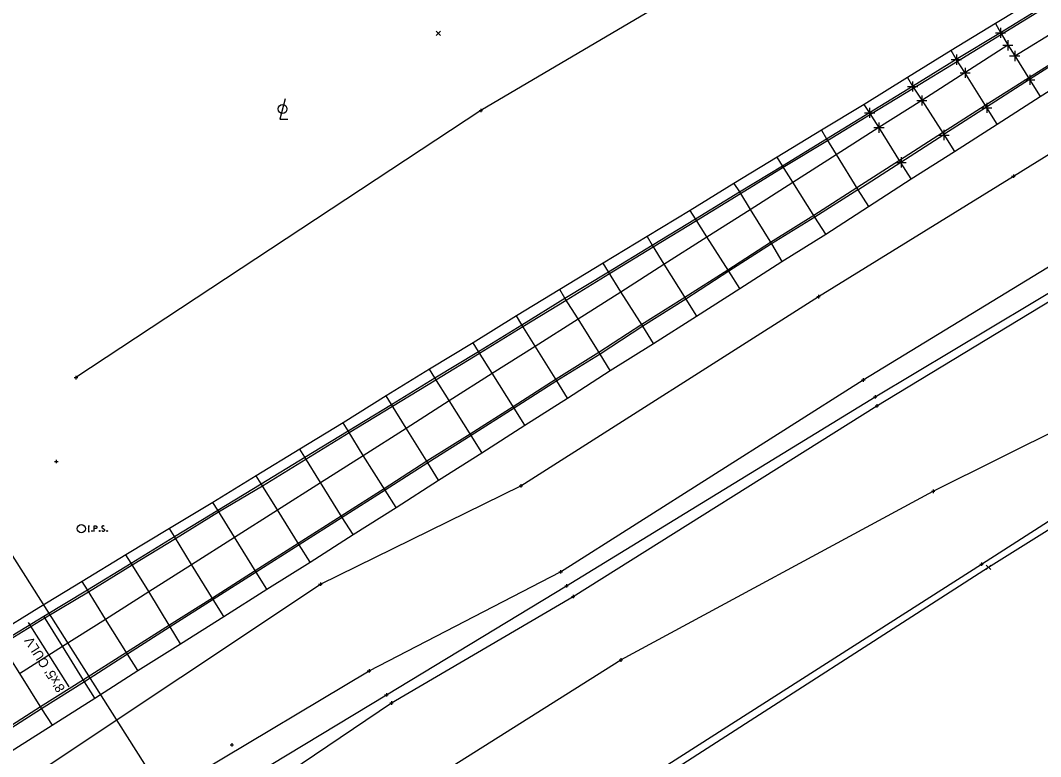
# Model space of a CAD drawing. Extents: x 207090 to 277928, y 600777 to 621109.
# Drawn here: x 261676.8 to 261977.3, y 611702.8 to 611919.6 of the extents above; entities that cross this region are included whole.
import ezdxf

# ---------------------------------------------------------------- set-up
doc = ezdxf.new("R2010")
doc.units = 0
for name, color, linetype in [('DR_X_Culvert', 7, 'Continuous'), ('DR_X_Ditch', 7, 'Continuous'), ('DR_X_Text', 7, 'Continuous'), ('LT_X_Poles', 7, 'Continuous'), ('PM_P_Dotted_Line', 7, 'Continuous'), ('PM_P_Edge_Line', 7, 'Continuous'), ('PM_P_Lane_Line', 7, 'Continuous'), ('PM_P_Stop_Line', 7, 'Continuous'), ('PM_X_Edge_Line', 7, 'Continuous'), ('PV_X_EOP', 7, 'Continuous'), ('PV_X_Joint', 7, 'Continuous'), ('PV_X_Shoulder', 7, 'Continuous'), ('SC_ProfileRun2', 7, 'Continuous'), ('SV_X_LiDAR_Check_Spots', 7, 'Continuous'), ('SV_X_Terrain_Boundary', 7, 'Continuous'), ('SV_X_Toe_of_Slope', 7, 'Continuous')]:
    doc.layers.add(name, color=color, linetype=linetype)

msp = doc.modelspace()

# ---------------------------------------------------------------- linework, layer by layer
at = {"layer": 'DR_X_Culvert'}
msp.add_line((261715.99, 611696.51), (261667.47, 611772.86), dxfattribs=at)
at = {"layer": 'DR_X_Ditch'}
msp.add_lwpolyline([(261132.11, 611543.06), (261151.34, 611551.01), (261204.82, 611549.24), (261275.42, 611542.1), (261338.97, 611540.56), (261396.89, 611545.27), (261464.5, 611556.09), (261526.91, 611576.88), (261579.68, 611599.94), (261643.38, 611630.11), (261702.06, 611671.1), (261784.56, 611720.96), (261837.63, 611753.06), (261928.54, 611808.72), (261986.01, 611843.07), (262043.42, 611883.09), (262136.97, 611939.5), (262196.81, 611979.61), (262342.79, 612067.36), (262434.39, 612121.89), (262514.3, 612151.84), (262581.31, 612172.43), (262656.49, 612183.09)], dxfattribs=at)
at = {"layer": 'DR_X_Text'}
msp.add_line((261679.01, 611742.21), (261691, 611723.34), dxfattribs=at)
at = {"layer": 'LT_X_Poles'}
msp.add_lwpolyline([(261754.78, 611896.47), (261753.2, 611890.49), (261755.57, 611890.49)], dxfattribs=at)
msp.add_circle((261753.99, 611893.52), 1.3, dxfattribs=at)
at = {"layer": 'PM_P_Dotted_Line'}
for points in [[(261696.72, 611770.7), (261697.08, 611770.7)], [(261696.72, 611769.1), (261697.08, 611769.1)], [(261696.9, 611769.1), (261696.9, 611770.7)], [(261697.86, 611769.31), (261697.92, 611769.31), (261697.95, 611769.28), (261697.98, 611769.23), (261697.98, 611769.17), (261697.95, 611769.12), (261697.92, 611769.1), (261697.86, 611769.1), (261697.83, 611769.12), (261697.79, 611769.17), (261697.79, 611769.23), (261697.83, 611769.28), (261697.86, 611769.31)], [(261698.47, 611769.1), (261698.47, 611770.7), (261699, 611770.7), (261699.05, 611770.68), (261699.13, 611770.66), (261699.16, 611770.63), (261699.19, 611770.61), (261699.24, 611770.54), (261699.27, 611770.48), (261699.29, 611770.38), (261699.29, 611770.23), (261699.28, 611770.18), (261699.26, 611770.1), (261699.22, 611770.02), (261699.17, 611769.98), (261699.14, 611769.95), (261699.08, 611769.93), (261699, 611769.91), (261698.47, 611769.91)], [(261700.11, 611769.31), (261700.16, 611769.31), (261700.2, 611769.28), (261700.23, 611769.23), (261700.23, 611769.17), (261700.2, 611769.12), (261700.16, 611769.1), (261700.11, 611769.1), (261700.08, 611769.12), (261700.04, 611769.17), (261700.04, 611769.23), (261700.08, 611769.28), (261700.11, 611769.31)], [(261701.48, 611770.58), (261701.45, 611770.61), (261701.42, 611770.63), (261701.32, 611770.67), (261701.2, 611770.7), (261701.11, 611770.7), (261701.08, 611770.7), (261700.94, 611770.66), (261700.81, 611770.58), (261700.74, 611770.48), (261700.72, 611770.38), (261700.72, 611770.3), (261700.74, 611770.2), (261700.83, 611770.12), (261701.43, 611769.74), (261701.49, 611769.69), (261701.51, 611769.64), (261701.53, 611769.56), (261701.53, 611769.49), (261701.52, 611769.41), (261701.51, 611769.36), (261701.49, 611769.3), (261701.46, 611769.25), (261701.44, 611769.21), (261701.41, 611769.17), (261701.38, 611769.15), (261701.33, 611769.12), (261701.3, 611769.11), (261701.2, 611769.1), (261701.05, 611769.1), (261700.95, 611769.12), (261700.8, 611769.21), (261700.72, 611769.28)], [(261702.29, 611769.31), (261702.35, 611769.31), (261702.38, 611769.28), (261702.41, 611769.23), (261702.41, 611769.17), (261702.38, 611769.12), (261702.35, 611769.1), (261702.29, 611769.1), (261702.26, 611769.12), (261702.23, 611769.17), (261702.23, 611769.23), (261702.26, 611769.28), (261702.29, 611769.31)]]:
    msp.add_lwpolyline(points, dxfattribs=at)
msp.add_circle((261694.71, 611769.89), 1.2, dxfattribs=at)
at = {"layer": 'PM_P_Edge_Line'}
for points in [[(261095.2, 611517.38), (261109.55, 611556.21), (261131.91, 611573.68), (261149.08, 611575.07), (261202.59, 611571.64), (261280.97, 611564.25), (261338.62, 611565.1), (261393.58, 611575.38), (261461.16, 611589.52), (261517.96, 611607.33), (261562.93, 611628.5), (261627.57, 611664.18), (261682.84, 611698.73), (261765.12, 611753.52), (261824.13, 611782.52), (261911.81, 611838.23), (261969.24, 611873.72), (262025.82, 611908.8), (262125.41, 611964.66), (262182.53, 612002.94), (262326.11, 612091.51)], [(261150.65, 611386.42), (261155.64, 611444.15), (261157.57, 611491.18), (261209.46, 611500.37), (261264.83, 611505.15), (261342.34, 611500.54), (261398.44, 611505.87), (261472.12, 611523.34), (261533.41, 611542.89), (261595.48, 611569.82), (261660.17, 611598), (261726.83, 611640.47), (261794.94, 611694.24), (261853.6, 611731.21), (261945.61, 611780.89), (262004.28, 611810.1), (262064.35, 611850.74), (262127.57, 611893.89), (262159.14, 611906.07), (262217.33, 611944.84), (262360.65, 612038.77)]]:
    msp.add_lwpolyline(points, dxfattribs=at)
at = {"layer": 'PM_P_Lane_Line'}
msp.add_lwpolyline([(261153.94, 611385.97), (261160.28, 611443.31), (261165.11, 611483.68), (261209.25, 611484.8), (261264.74, 611486.28), (261342.14, 611487.48), (261398.74, 611488.7), (261481.71, 611501.24), (261537, 611521.16), (261606, 611546.1), (261656.85, 611565.67), (261670.38, 611573.79), (261742.74, 611619.98), (261811.92, 611664.95), (261868.59, 611701.14), (261959.9, 611759.42), (262013.54, 611793.87), (262076.54, 611833.59), (262168.76, 611888.84), (262184.39, 611898.2), (262204.83, 611910.25), (262363.11, 611892.31)], dxfattribs=at)
at = {"layer": 'PM_P_Stop_Line'}
for p, q in [((261811.86, 611893.04), (261812.86, 611893.04)), ((261812.36, 611893.54), (261812.36, 611892.54)), ((261812.36, 611893.04), (261812.36, 611893.04)), ((261968.74, 611873.72), (261969.74, 611873.72)), ((261969.24, 611874.22), (261969.24, 611873.22)), ((261969.24, 611873.72), (261969.24, 611873.72)), ((261911.31, 611838.23), (261912.31, 611838.23)), ((261911.81, 611838.73), (261911.81, 611837.73)), ((261911.81, 611838.23), (261911.81, 611838.23)), ((261692.64, 611814.37), (261693.64, 611814.37)), ((261693.14, 611814.87), (261693.14, 611813.87)), ((261693.14, 611814.37), (261693.14, 611814.37)), ((261924.55, 611813.69), (261925.55, 611813.69)), ((261925.05, 611814.19), (261925.05, 611813.19)), ((261925.05, 611813.69), (261925.05, 611813.69)), ((261928.04, 611808.72), (261929.04, 611808.72)), ((261928.54, 611809.22), (261928.54, 611808.22)), ((261928.54, 611808.72), (261928.54, 611808.72)), ((261928.57, 611806.04), (261929.57, 611806.04)), ((261929.07, 611806.54), (261929.07, 611805.54)), ((261929.07, 611806.04), (261929.07, 611806.04)), ((261823.63, 611782.52), (261824.63, 611782.52)), ((261824.13, 611783.02), (261824.13, 611782.02)), ((261824.13, 611782.52), (261824.13, 611782.52)), ((261945.11, 611780.89), (261946.11, 611780.89)), ((261945.61, 611781.39), (261945.61, 611780.39)), ((261945.61, 611780.89), (261945.61, 611780.89)), ((261959.4, 611759.42), (261960.4, 611759.42)), ((261959.9, 611759.92), (261959.9, 611758.92)), ((261959.9, 611759.42), (261959.9, 611759.42)), ((261835.4, 611757.16), (261836.4, 611757.16)), ((261835.9, 611757.66), (261835.9, 611756.66)), ((261835.9, 611757.16), (261835.9, 611757.16)), ((261764.62, 611753.52), (261765.62, 611753.52)), ((261765.12, 611754.02), (261765.12, 611753.02)), ((261765.12, 611753.52), (261765.12, 611753.52)), ((261837.63, 611753.56), (261837.63, 611752.56)), ((261837.13, 611753.06), (261838.13, 611753.06)), ((261837.63, 611753.06), (261837.63, 611753.06)), ((261839.61, 611750.39), (261839.61, 611749.39)), ((261839.11, 611749.89), (261840.11, 611749.89)), ((261839.61, 611749.89), (261839.61, 611749.89)), ((261853.1, 611731.21), (261854.1, 611731.21)), ((261853.6, 611731.71), (261853.6, 611730.71)), ((261853.6, 611731.21), (261853.6, 611731.21)), ((261778.95, 611728.01), (261779.95, 611728.01)), ((261779.45, 611728.51), (261779.45, 611727.51)), ((261779.45, 611728.01), (261779.45, 611728.01)), ((261784.06, 611720.96), (261785.06, 611720.96)), ((261784.56, 611721.46), (261784.56, 611720.46)), ((261784.56, 611720.96), (261784.56, 611720.96)), ((261785.6, 611718.54), (261786.6, 611718.54)), ((261786.1, 611719.04), (261786.1, 611718.04)), ((261786.1, 611718.54), (261786.1, 611718.54))]:
    msp.add_line(p, q, dxfattribs=at)
at = {"layer": 'PM_X_Edge_Line'}
for p, q in [((261799.22, 611915.14), (261800.55, 611916.48)), ((261799.22, 611916.48), (261800.55, 611915.14)), ((261961.23, 611757.84), (261962.57, 611759.18)), ((261961.23, 611759.18), (261962.57, 611757.84))]:
    msp.add_line(p, q, dxfattribs=at)
for points in [[(261671.16, 611735.77), (261684, 611743.61), (261696.86, 611751.28), (261709.72, 611759.19), (261722.48, 611767.02), (261735.16, 611774.85), (261748.05, 611782.52), (261760.83, 611790.38), (261773.6, 611798.18), (261786.4, 611806.01), (261799.18, 611813.78), (261811.99, 611821.61), (261824.79, 611829.47), (261837.51, 611837.22), (261850.31, 611845.08), (261863.19, 611852.87), (261875.94, 611860.67), (261888.85, 611868.58), (261901.48, 611876.33), (261914.47, 611884.22), (261927.2, 611892.01), (261939.92, 611899.74), (261952.77, 611907.64), (261965.72, 611915.54), (261979.19, 611923.84)], [(261987.04, 611911.02), (261973.73, 611902.58), (261960.97, 611894.57), (261948.41, 611886.44), (261935.72, 611878.33), (261923.12, 611870.27), (261910.43, 611862.14), (261897.73, 611854.15), (261885.18, 611846.05), (261872.49, 611837.95), (261859.82, 611829.99), (261847.16, 611821.82), (261834.56, 611813.88), (261821.93, 611805.77), (261809.26, 611797.74), (261796.5, 611789.75), (261783.94, 611781.62), (261771.23, 611773.59), (261758.6, 611765.54), (261745.94, 611757.51), (261733.31, 611749.45), (261720.64, 611741.44), (261707.99, 611733.42), (261695.31, 611725.36), (261682.69, 611717.38), (261669.95, 611709.28)]]:
    msp.add_lwpolyline(points, dxfattribs=at)
at = {"layer": 'PV_X_EOP'}
for points in [[(261977.36, 611926.85), (261963.96, 611918.66), (261950.93, 611910.7), (261938.09, 611902.8), (261925.33, 611894.88), (261912.73, 611887.26), (261899.71, 611879.33), (261886.93, 611871.58), (261874.07, 611863.63), (261861.34, 611855.98), (261848.38, 611848.08), (261835.62, 611840.33), (261822.93, 611832.57), (261810.09, 611824.67), (261797.24, 611816.86), (261784.54, 611809.03), (261771.88, 611801.07), (261759.09, 611793.3), (261746.24, 611785.48), (261733.45, 611777.61), (261720.73, 611769.93), (261707.8, 611762.18), (261694.96, 611754.32), (261682.21, 611746.6), (261669.39, 611738.7)], [(261673.28, 611703.86), (261686.12, 611712.05), (261698.69, 611719.95), (261711.39, 611728.07), (261723.96, 611735.96), (261736.7, 611744.03), (261749.35, 611752.05), (261762.07, 611760.02), (261774.74, 611768.21), (261787.41, 611776.13), (261799.93, 611784.15), (261812.7, 611792.25), (261825.32, 611800.39), (261837.94, 611808.33), (261850.46, 611816.48), (261863.23, 611824.47), (261875.92, 611832.52), (261888.64, 611840.61), (261901.06, 611848.61), (261913.98, 611856.68), (261926.58, 611864.79), (261939.15, 611872.89), (261951.92, 611880.98), (261964.51, 611889), (261977.18, 611897.17), (261990.4, 611905.54)]]:
    msp.add_lwpolyline(points, dxfattribs=at)
at = {"layer": 'PV_X_Joint'}
msp.add_line((261923.45, 611869.73), (261948.72, 611885.95), dxfattribs=at)
for points in [[(261969.67, 611909.16), (261983.14, 611917.37), (261996.1, 611925.21), (262008.82, 611933.05), (262021.68, 611940.97), (262034.35, 611948.61), (262047.25, 611956.47), (262060.1, 611964.3), (262072.81, 611971.98), (262085.45, 611979.77), (262098.39, 611987.63), (262111.17, 611995.43), (262123.99, 612003.24), (262136.83, 612011.09), (262149.61, 612018.97), (262162.63, 612026.86), (262175.23, 612034.57), (262188.24, 612042.4), (262201.02, 612050.15), (262213.81, 612057.93), (262226.71, 612065.72), (262239.38, 612073.54)], [(262243.57, 612066.59), (262230.75, 612058.86), (262217.78, 612051.06), (262205.03, 612043.31), (262192.24, 612035.51), (262179.39, 612027.69), (262166.53, 612019.86), (262153.73, 612012.08), (262140.88, 612004.22), (262127.96, 611996.3), (262115.21, 611988.56), (262102.49, 611980.81), (262089.66, 611973.04), (262076.89, 611965.25), (262064.18, 611957.49), (262051.34, 611949.71), (262038.5, 611941.83), (262025.79, 611934.15), (262012.96, 611926.27), (262000.04, 611918.42), (261987.29, 611910.61), (261974, 611902.15), (261961.33, 611894), (261948.72, 611885.95)], [(261926.92, 611892.44), (261939.58, 611900.25), (261952.43, 611908.17), (261965.41, 611916.06), (261978.9, 611924.32)], [(261963.96, 611918.66), (261965.41, 611916.06), (261967.62, 611912.4), (261969.67, 611909.16), (261974, 611902.15), (261977.18, 611897.17)], [(261676.53, 611727.24), (261689.15, 611735.26), (261701.8, 611743.24), (261714.57, 611751.34), (261727.17, 611759.36), (261739.83, 611767.41), (261752.48, 611775.39), (261765.13, 611783.45), (261777.76, 611791.47), (261790.38, 611799.52), (261803.08, 611807.62), (261815.72, 611815.67), (261828.43, 611823.69), (261841.01, 611831.72), (261853.67, 611839.68), (261866.33, 611847.77), (261879, 611855.85), (261891.69, 611863.93), (261904.25, 611871.96), (261917.03, 611880.09), (261929.62, 611888.16), (261942.25, 611896.15), (261954.93, 611904.24), (261967.62, 611912.4)], [(261964.51, 611889), (261961.33, 611894), (261954.93, 611904.24), (261952.43, 611908.17), (261950.93, 611910.7)], [(261938.09, 611902.8), (261939.58, 611900.25), (261942.25, 611896.15), (261948.72, 611885.95), (261951.92, 611880.98)], [(261939.15, 611872.89), (261936.04, 611877.81), (261929.62, 611888.16), (261926.92, 611892.44), (261925.33, 611894.88)], [(261670.85, 611736.27), (261683.69, 611744.1), (261696.49, 611751.89), (261709.38, 611759.74), (261722.15, 611767.54), (261734.87, 611775.31), (261747.69, 611783.1), (261760.5, 611790.91), (261773.28, 611798.7), (261786.1, 611806.49), (261798.85, 611814.31), (261811.68, 611822.1), (261824.47, 611829.97), (261837.16, 611837.76), (261850.01, 611845.56), (261862.86, 611853.39), (261875.62, 611861.17), (261888.54, 611869.07), (261901.21, 611876.76), (261914.16, 611884.72), (261926.92, 611892.44)], [(261912.73, 611887.26), (261914.16, 611884.72), (261917.03, 611880.09), (261923.45, 611869.73), (261926.58, 611864.79)], [(261913.98, 611856.68), (261910.72, 611861.68), (261904.25, 611871.96), (261901.21, 611876.76), (261899.71, 611879.33)], [(261886.93, 611871.58), (261888.54, 611869.07), (261891.69, 611863.93), (261897.96, 611853.76), (261901.06, 611848.61)], [(261923.45, 611869.73), (261910.72, 611861.68), (261897.96, 611853.76), (261885.39, 611845.72), (261872.79, 611837.48), (261860.08, 611829.58), (261847.49, 611821.28), (261834.82, 611813.46), (261822.17, 611805.38), (261809.54, 611797.29), (261796.82, 611789.24), (261784.21, 611781.2), (261771.5, 611773.16), (261758.87, 611765.11), (261746.2, 611757.08), (261733.58, 611749.02), (261720.92, 611740.98), (261708.28, 611732.97), (261695.66, 611724.79), (261683.01, 611716.86), (261670.27, 611708.76)], [(261888.64, 611840.61), (261885.39, 611845.72), (261879, 611855.85), (261875.62, 611861.17), (261874.07, 611863.63)], [(261861.34, 611855.98), (261862.86, 611853.39), (261866.33, 611847.77), (261872.79, 611837.48), (261875.92, 611832.52)], [(261863.23, 611824.47), (261860.08, 611829.58), (261853.67, 611839.68), (261850.01, 611845.56), (261848.38, 611848.08)], [(261850.46, 611816.48), (261847.49, 611821.28), (261841.01, 611831.72), (261837.16, 611837.76), (261835.62, 611840.33)], [(261837.94, 611808.33), (261834.82, 611813.46), (261828.43, 611823.69), (261824.47, 611829.97), (261822.93, 611832.57)], [(261825.32, 611800.39), (261822.17, 611805.38), (261815.72, 611815.67), (261811.68, 611822.1), (261810.09, 611824.67)], [(261812.7, 611792.35), (261809.54, 611797.29), (261803.08, 611807.62), (261798.85, 611814.31), (261797.24, 611816.86)], [(261799.93, 611784.15), (261796.82, 611789.24), (261790.38, 611799.52), (261786.1, 611806.49), (261784.54, 611809.03)], [(261787.41, 611776.13), (261784.21, 611781.2), (261777.76, 611791.47), (261773.28, 611798.7), (261771.88, 611801.07)], [(261774.74, 611768.21), (261771.5, 611773.16), (261765.13, 611783.45), (261760.5, 611790.91), (261759.09, 611793.3)], [(261762.07, 611760.02), (261758.87, 611765.11), (261752.48, 611775.39), (261747.69, 611783.1), (261746.24, 611785.48)], [(261749.35, 611752.05), (261746.2, 611757.08), (261739.83, 611767.41), (261734.87, 611775.31), (261733.45, 611777.61)], [(261736.7, 611744.03), (261733.58, 611749.02), (261727.17, 611759.36), (261722.15, 611767.54), (261720.73, 611769.93)], [(261723.96, 611735.96), (261720.92, 611740.98), (261714.57, 611751.34), (261709.38, 611759.74), (261707.8, 611762.18)], [(261711.39, 611728.07), (261708.28, 611732.97), (261701.8, 611743.24), (261696.49, 611751.89), (261694.96, 611754.32)], [(261698.69, 611719.95), (261695.66, 611724.79), (261689.15, 611735.26), (261683.69, 611744.1)], [(261670.85, 611736.27), (261676.53, 611727.24), (261683.01, 611716.86), (261686.12, 611712.05)]]:
    msp.add_lwpolyline(points, dxfattribs=at)
at = {"layer": 'PV_X_Shoulder'}
msp.add_line((261969.67, 611909.16), (261969.64, 611909.14), dxfattribs=at)
at = {"layer": 'SC_ProfileRun2'}
for p, q in [((261686.84, 611789.68), (261687.84, 611789.68)), ((261687.34, 611790.18), (261687.34, 611789.18)), ((261687.34, 611789.68), (261687.34, 611789.68)), ((261738.54, 611706.2), (261739.54, 611706.2)), ((261739.04, 611706.7), (261739.04, 611705.7)), ((261739.04, 611706.2), (261739.04, 611706.2))]:
    msp.add_line(p, q, dxfattribs=at)
at = {"layer": 'SV_X_LiDAR_Check_Spots'}
for p, q in [((261963.95, 611915.96), (261966.95, 611915.96)), ((261965.45, 611917.46), (261965.45, 611914.46)), ((261965.45, 611915.96), (261965.45, 611915.96)), ((261967.63, 611913.78), (261967.63, 611910.78)), ((261952.47, 611909.54), (261952.47, 611906.54)), ((261966.13, 611912.28), (261969.13, 611912.28)), ((261967.63, 611912.28), (261967.63, 611912.28)), ((261969.64, 611910.64), (261969.64, 611907.64)), ((261950.97, 611908.04), (261953.97, 611908.04)), ((261952.47, 611908.04), (261952.47, 611908.04)), ((261968.14, 611909.14), (261971.14, 611909.14)), ((261969.64, 611909.14), (261969.64, 611909.14)), ((261953.54, 611904.15), (261956.54, 611904.15)), ((261955.04, 611905.65), (261955.04, 611902.65)), ((261955.04, 611904.15), (261955.04, 611904.15)), ((261974.07, 611903.58), (261974.07, 611900.58)), ((261939.56, 611901.65), (261939.56, 611898.65)), ((261972.57, 611902.08), (261975.57, 611902.08)), ((261974.07, 611902.08), (261974.07, 611902.08)), ((261938.06, 611900.15), (261941.06, 611900.15)), ((261939.56, 611900.15), (261939.56, 611900.15)), ((261942.29, 611897.52), (261942.29, 611894.52)), ((261940.79, 611896.02), (261943.79, 611896.02)), ((261942.29, 611896.02), (261942.29, 611896.02)), ((261961.4, 611895.37), (261961.4, 611892.37)), ((261925.41, 611892.37), (261928.41, 611892.37)), ((261926.91, 611893.87), (261926.91, 611890.87)), ((261926.91, 611892.37), (261926.91, 611892.37)), ((261959.9, 611893.87), (261962.9, 611893.87)), ((261961.4, 611893.87), (261961.4, 611893.87)), ((261929.65, 611889.51), (261929.65, 611886.51)), ((261928.15, 611888.01), (261931.15, 611888.01)), ((261929.65, 611888.01), (261929.65, 611888.01)), ((261947.29, 611885.83), (261950.29, 611885.83)), ((261948.79, 611887.33), (261948.79, 611884.33)), ((261948.79, 611885.83), (261948.79, 611885.83)), ((261934.66, 611877.78), (261937.66, 611877.78)), ((261936.16, 611879.28), (261936.16, 611876.28)), ((261936.16, 611877.78), (261936.16, 611877.78))]:
    msp.add_line(p, q, dxfattribs=at)
at = {"layer": 'SV_X_Terrain_Boundary'}
msp.add_lwpolyline([(261670.38, 611573.79), (261744.36, 611617.34), (261814.33, 611663.74), (261869.18, 611698.9), (261961.9, 611758.51), (262015.3, 611791.96), (262079.06, 611831.97), (262076.54, 611833.59), (262168.76, 611888.84), (262184.39, 611898.2), (262204.83, 611910.25), (262363.11, 611892.31)], dxfattribs=at)
at = {"layer": 'SV_X_Toe_of_Slope'}
for points in [[(261729.51, 611698.17), (261779.45, 611728.01), (261835.9, 611757.16), (261925.05, 611813.69), (261983.11, 611849.16), (262040.29, 611887.78), (262135.2, 611943.79), (262193.94, 611983.59), (262339.69, 612072.56), (262431.52, 612127.67), (262513.25, 612156.24), (262580.26, 612177.17), (262655.37, 612187.35)], [(261135.4, 611543.42), (261151.99, 611545.22), (261205.95, 611544.69), (261267.18, 611537.07), (261340.59, 611536.02), (261398.29, 611542.06), (261464.98, 611551.3), (261527.41, 611569.91), (261584.17, 611593.02), (261647.78, 611623.35), (261706.85, 611665.06), (261786.1, 611718.54), (261839.61, 611749.89), (261929.07, 611806.04), (261986.89, 611841.11), (262047.29, 611878.6), (262138.86, 611935.4), (262200.14, 611972.99), (262344.06, 612064.28), (262436.85, 612118.36), (262514.09, 612148.95), (262582.72, 612168.49), (262657.34, 612178.41)], [(262283.04, 612168.99), (262271.51, 612147.23), (262176.6, 612102.62), (262080.36, 612054.77), (261984.45, 612003.37), (261899.63, 611944.52), (261812.36, 611893.04), (261693.14, 611814.37)]]:
    msp.add_lwpolyline(points, dxfattribs=at)

# ---------------------------------------------------------------- texts
at = {"layer": 'DR_X_Text'}
msp.add_text("8'x5' CULV", height=2.8, rotation=122.4417, dxfattribs=at).set_placement((261690.05, 611722.79))

doc.saveas('drawing.dxf')
